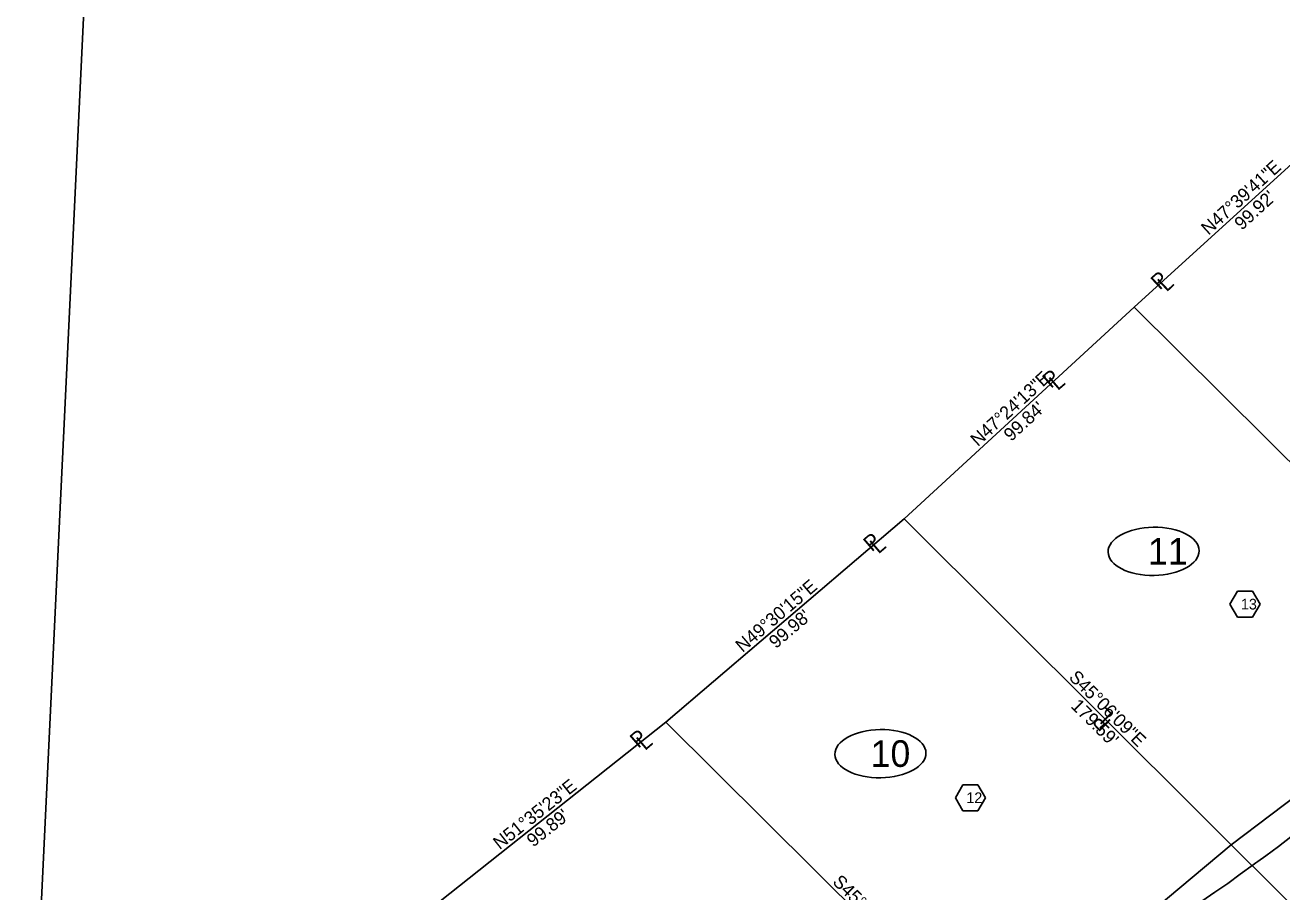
# Model space of a CAD drawing. Extents: x 1145508 to 2262867, y -3126236 to 2021677.
# Drawn here: x 1146802.7 to 1147204, y 2017209.5 to 2017486.3 of the extents above; entities that cross this region are included whole.
import ezdxf

# ---------------------------------------------------------------- set-up
doc = ezdxf.new("R2010")
doc.units = 0
for name, color, linetype in [('DSN_RDWY_Const Limits', 7, 'Continuous'), ('DSN_ROW_Annotation', 7, 'Continuous'), ('DSN_ROW_Line', 7, 'Continuous'), ('DSN_ROW_Line-Annotation', 7, 'Continuous'), ('DSN_ROW_Prop-Line', 7, 'Continuous'), ('DSN_ROW_Prop-Line-Annotation', 7, 'Continuous'), ('EX_SECTION', 7, 'Continuous'), ('EX_SUBDIV_ANNOT', 7, 'Continuous')]:
    doc.layers.add(name, color=color, linetype=linetype)

msp = doc.modelspace()

# ---------------------------------------------------------------- linework, layer by layer
at = {"layer": 'DSN_RDWY_Const Limits'}
msp.add_lwpolyline([(1147165.35, 2017197.55), (1147165.93, 2017197.98), (1147170.07, 2017200.82), (1147171.13, 2017201.54), (1147171.61, 2017201.87), (1147174.22, 2017203.65), (1147178.36, 2017206.48), (1147182.5, 2017209.32), (1147183.48, 2017209.98), (1147184.12, 2017210.42), (1147186.65, 2017212.15), (1147190.69, 2017215.11), (1147194.74, 2017218.06), (1147195.69, 2017218.73), (1147196.32, 2017219.18), (1147198.81, 2017220.97), (1147202.85, 2017223.93), (1147206.77, 2017227.04)], dxfattribs=at)
at = {"layer": 'DSN_ROW_Line'}
for p, q in [((1147187.77, 2017224.53), (1147268.17, 2017285.46)), ((1147111.19, 2017160.48), (1147187.77, 2017224.53))]:
    msp.add_line(p, q, dxfattribs=at)
at = {"layer": 'DSN_ROW_Line-Annotation'}
for centre in [(1147163.01, 2017318.21), (1147075.77, 2017253.59)]:
    msp.add_ellipse(centre, major_axis=(14.54, 0.23), ratio=0.529773, dxfattribs=at)
at = {"layer": 'DSN_ROW_Prop-Line'}
for p, q in [((1147156.81, 2017396.18), (1147230.67, 2017463.48)), ((1147083.32, 2017328.61), (1147156.81, 2017396.18)), ((1147156.81, 2017396.18), (1147284.33, 2017269.39)), ((1147007.29, 2017263.68), (1147083.32, 2017328.61)), ((1147083.32, 2017328.61), (1147210.54, 2017201.84)), ((1146929.01, 2017201.62), (1147007.29, 2017263.68)), ((1147007.29, 2017263.68), (1147135.67, 2017136.17))]:
    msp.add_line(p, q, dxfattribs=at)
at = {"layer": 'EX_SECTION'}
msp.add_line((1146895.16, 2019036.08), (1146802.69, 2017096.93), dxfattribs=at)
at = {"layer": 'EX_SUBDIV_ANNOT'}
for p, q in [((1147187.38, 2017301.36), (1147189.78, 2017305.52)), ((1147189.78, 2017305.52), (1147194.58, 2017305.52)), ((1147194.58, 2017305.52), (1147196.98, 2017301.36)), ((1147189.78, 2017297.2), (1147187.38, 2017301.36)), ((1147196.98, 2017301.36), (1147194.58, 2017297.2)), ((1147194.58, 2017297.2), (1147189.78, 2017297.2)), ((1147099.71, 2017239.52), (1147102.11, 2017243.67)), ((1147102.11, 2017243.67), (1147106.91, 2017243.67)), ((1147106.91, 2017243.67), (1147109.31, 2017239.52)), ((1147102.11, 2017235.36), (1147099.71, 2017239.52)), ((1147109.31, 2017239.52), (1147106.91, 2017235.36)), ((1147106.91, 2017235.36), (1147102.11, 2017235.36))]:
    msp.add_line(p, q, dxfattribs=at)

# ---------------------------------------------------------------- texts
at = {"layer": 'DSN_ROW_Annotation'}
for s, rotation, p in [('N47°39\'41"E', 42.3387, (1147180.53, 2017419.01)), ("99.92'", 42.3387, (1147191.15, 2017420.57)), ('N47°24\'13"E', 42.5965, (1147106.9, 2017351.51)), ("99.84'", 42.5965, (1147117.51, 2017353.12)), ('N49°30\'15"E', 40.4959, (1147031.75, 2017285.75)), ("99.98'", 40.4959, (1147042.41, 2017286.97)), ('S45°06\'09"E', 315.1025, (1147135.69, 2017277.69)), ("179.59'", 315.1025, (1147136.34, 2017268.57)), ('N51°35\'23"E', 38.4103, (1146954.22, 2017222.76)), ("99.89'", 38.4103, (1146964.93, 2017223.59)), ('S45°11\'39"E', 315.1941, (1147060.22, 2017212.38))]:
    msp.add_text(s, height=4.2, rotation=rotation, dxfattribs=at).set_placement(p)
at = {"layer": 'DSN_ROW_Line-Annotation'}
for s, p in [('11', (1147161.23, 2017314)), ('10', (1147072.67, 2017249.38))]:
    msp.add_text(s, height=8.5, dxfattribs=at).set_placement(p)
at = {"layer": 'DSN_ROW_Prop-Line-Annotation'}
for s, rotation, p in [('P', 43.2, (1147164.98, 2017401.46)), ('L', 43.2, (1147167.14, 2017400.86)), ('P', 40.5823, (1147130.21, 2017370.07)), ('L', 40.5823, (1147132.35, 2017369.37)), ('P', 40.5823, (1147073.01, 2017317.89)), ('L', 40.5823, (1147075.14, 2017317.19)), ('P', 135.169, (1147149.7, 2017263.89)), ('L', 135.169, (1147150.22, 2017266.07)), ('P', 40.5823, (1146998.47, 2017255.1)), ('L', 40.5823, (1147000.6, 2017254.41))]:
    msp.add_text(s, height=5, rotation=rotation, dxfattribs=at).set_placement(p)
at = {"layer": 'EX_SUBDIV_ANNOT'}
for s, p in [('13', (1147190.88, 2017299.65)), ('12', (1147103.2, 2017237.81))]:
    msp.add_text(s, height=3.418, dxfattribs=at).set_placement(p)

doc.saveas('drawing.dxf')
